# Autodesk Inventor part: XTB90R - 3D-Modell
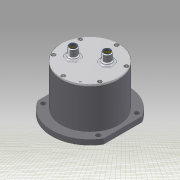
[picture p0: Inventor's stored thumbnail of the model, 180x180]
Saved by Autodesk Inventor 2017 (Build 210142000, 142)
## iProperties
Category: Winkelsensor
Company: IBS-Hühne GmbH
Created: 2016-06
Part Number: XTB90R - 3D-Modell
Project: XTB90R
Material: AlMgSi1, schwarz eloxiert
Description: XT00000118
Vendor: IBS-Hühne GmbH
Document SubType Name: Modeling
Designer: Geisbauer
Stock Number: IBSMT65
Mass: 1279.12 g
Surface Area: 458.674 cm^2
Volume: 473.749 cm^3
Density: 2.7 g/cm^3
Appearance: Aluminum (schwarz eloxiert)
SaveDate: 2010-04-11
SaveTime: 09:56
FileName: IBS0000094 - IBS Vorlage Bauteil
TotalMass: 0
TotalVolume: 0 mm^3
Title: 3D-Modell
Subject: XTB90R
Comments: IBS-Hühne GmbH Industriestraße 29  76287 Rheinstetten info@ibs.huehne.de
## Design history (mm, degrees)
derived "IBSMT65_.ipt"
feature "Volumenkörper1::IBSMT65_.ipt" dims "d1" = 10
tag "Bezeichnung2"
node "Volumenkörper2"
